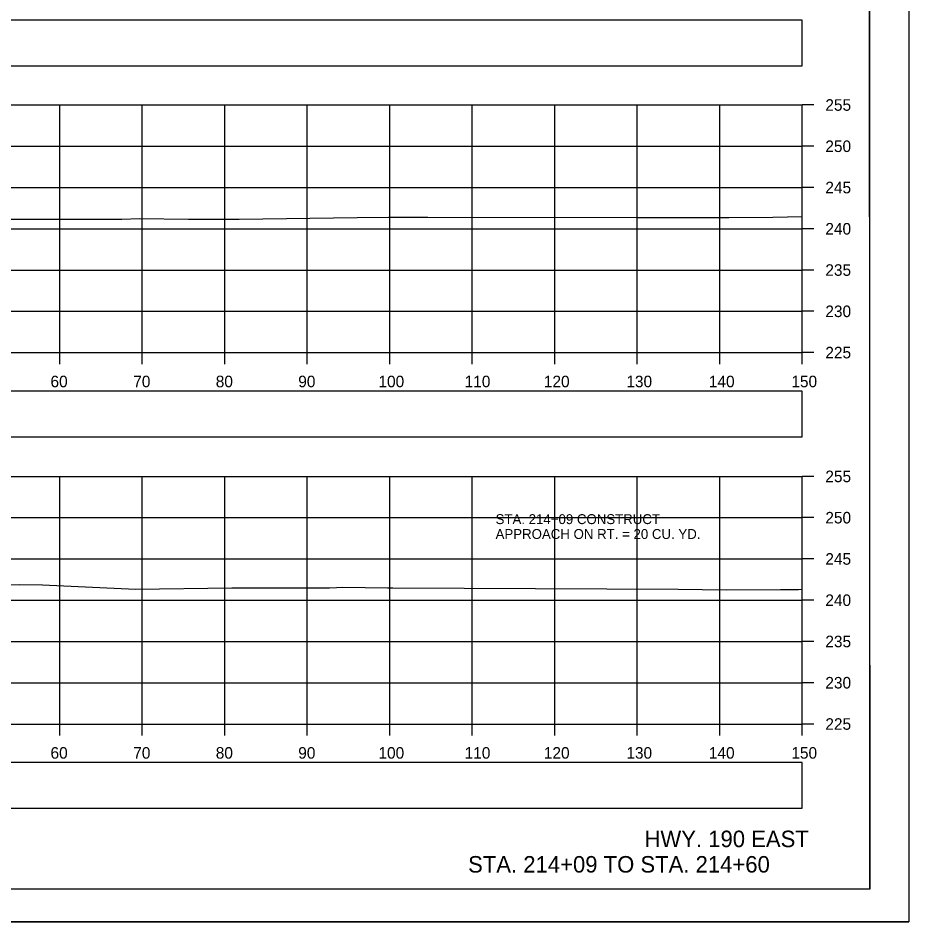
# Model space of a CAD drawing. Extents: x 1369627 to 1374022, y 380035 to 398173.
# Drawn here: x 1372153.5 to 1372261.5, y 383238.9 to 383348.4 of the extents above; entities that cross this region are included whole.
import ezdxf

# ---------------------------------------------------------------- set-up
doc = ezdxf.new("R2010")
doc.units = 0
for name, color, linetype in [('Default', 7, 'Continuous'), ('R_Axis', 7, 'Continuous'), ('R_Axis Annot', 7, 'Continuous'), ('R_Border', 7, 'Continuous'), ('R_Draft', 7, 'Continuous'), ('R_Exist Surface', 7, 'Continuous'), ('R_Grid', 7, 'Continuous'), ('R_No Plot', 7, 'Continuous'), ('R_Water', 7, 'Continuous')]:
    doc.layers.add(name, color=color, linetype=linetype)

msp = doc.modelspace()

# ---------------------------------------------------------------- linework, layer by layer
at = {"layer": 'Default'}
for points in [[(1371948.53, 383342.59), (1372248.53, 383342.59), (1372248.53, 383348.11), (1371948.53, 383348.11)], [(1371948.53, 383297.62), (1372248.53, 383297.62), (1372248.53, 383303.14), (1371948.53, 383303.14)], [(1371948.53, 383252.65), (1372248.53, 383252.65), (1372248.53, 383258.17), (1371948.53, 383258.17)]]:
    msp.add_lwpolyline(points, close=True, dxfattribs=at)
at = {"layer": 'R_Axis'}
for p, q in [((1372248.53, 383307.83), (1372248.53, 383337.83)), ((1372249.93, 383337.83), (1372248.53, 383337.83)), ((1372249.93, 383332.83), (1372248.53, 383332.83)), ((1372249.93, 383327.83), (1372248.53, 383327.83)), ((1372249.93, 383322.83), (1372248.53, 383322.83)), ((1372249.93, 383317.83), (1372248.53, 383317.83)), ((1372249.93, 383312.83), (1372248.53, 383312.83)), ((1371948.53, 383307.83), (1372248.53, 383307.83)), ((1372158.53, 383306.43), (1372158.53, 383307.83)), ((1372168.53, 383306.43), (1372168.53, 383307.83)), ((1372178.53, 383306.43), (1372178.53, 383307.83)), ((1372188.53, 383306.43), (1372188.53, 383307.83)), ((1372198.53, 383306.43), (1372198.53, 383307.83)), ((1372208.53, 383306.43), (1372208.53, 383307.83)), ((1372218.53, 383306.43), (1372218.53, 383307.83)), ((1372228.53, 383306.43), (1372228.53, 383307.83)), ((1372238.53, 383306.43), (1372238.53, 383307.83)), ((1372248.53, 383306.43), (1372248.53, 383307.83)), ((1372249.93, 383307.83), (1372248.53, 383307.83)), ((1372248.53, 383262.83), (1372248.53, 383292.83)), ((1372249.93, 383292.83), (1372248.53, 383292.83)), ((1372249.93, 383287.83), (1372248.53, 383287.83)), ((1372249.93, 383282.83), (1372248.53, 383282.83)), ((1372249.93, 383277.83), (1372248.53, 383277.83)), ((1372249.93, 383272.83), (1372248.53, 383272.83)), ((1372249.93, 383267.83), (1372248.53, 383267.83)), ((1371948.53, 383262.83), (1372248.53, 383262.83)), ((1372158.53, 383261.43), (1372158.53, 383262.83)), ((1372168.53, 383261.43), (1372168.53, 383262.83)), ((1372178.53, 383261.43), (1372178.53, 383262.83)), ((1372188.53, 383261.43), (1372188.53, 383262.83)), ((1372198.53, 383261.43), (1372198.53, 383262.83)), ((1372208.53, 383261.43), (1372208.53, 383262.83)), ((1372218.53, 383261.43), (1372218.53, 383262.83)), ((1372228.53, 383261.43), (1372228.53, 383262.83)), ((1372238.53, 383261.43), (1372238.53, 383262.83)), ((1372248.53, 383261.43), (1372248.53, 383262.83)), ((1372249.93, 383262.83), (1372248.53, 383262.83))]:
    msp.add_line(p, q, dxfattribs=at)
at = {"layer": 'R_Border'}
for q in [(1372256.71, 383448.29), (1371940.53, 383242.83)]:
    msp.add_line((1372256.71, 383242.83), q, dxfattribs=at)
at = {"layer": 'R_Exist Surface'}
for points in [[(1372150.68, 383324.01), (1372162.03, 383324.01), (1372166.04, 383323.98), (1372168.2, 383324.06), (1372174.12, 383323.99), (1372180.28, 383323.98), (1372194.59, 383324.2), (1372198.38, 383324.25), (1372203.14, 383324.25), (1372228.62, 383324.18), (1372239.38, 383324.21), (1372239.62, 383324.21), (1372239.65, 383324.21), (1372244.97, 383324.23), (1372248.53, 383324.31)], [(1372145.41, 383279.71), (1372153.63, 383279.73), (1372156.43, 383279.7), (1372167.73, 383279.17), (1372179.41, 383279.31), (1372191.24, 383279.33), (1372192.07, 383279.38), (1372192.85, 383279.4), (1372198.25, 383279.31), (1372198.54, 383279.31), (1372198.89, 383279.31), (1372233.5, 383279.17), (1372239.31, 383279.08), (1372245.88, 383279.13), (1372248.08, 383279.14), (1372248.53, 383279.15)]]:
    msp.add_lwpolyline(points, dxfattribs=at)
at = {"layer": 'R_Grid'}
for p, q in [((1371948.53, 383337.83), (1372248.53, 383337.83)), ((1372158.53, 383307.83), (1372158.53, 383337.83)), ((1372168.53, 383307.83), (1372168.53, 383337.83)), ((1372178.53, 383307.83), (1372178.53, 383337.83)), ((1372188.53, 383307.83), (1372188.53, 383337.83)), ((1372198.53, 383307.83), (1372198.53, 383337.83)), ((1372208.53, 383307.83), (1372208.53, 383337.83)), ((1372218.53, 383307.83), (1372218.53, 383337.83)), ((1372228.53, 383307.83), (1372228.53, 383337.83)), ((1372238.53, 383307.83), (1372238.53, 383337.83)), ((1372248.53, 383307.83), (1372248.53, 383337.83)), ((1371948.53, 383332.83), (1372248.53, 383332.83)), ((1371948.53, 383327.83), (1372248.53, 383327.83)), ((1371948.53, 383322.83), (1372248.53, 383322.83)), ((1371948.53, 383317.83), (1372248.53, 383317.83)), ((1371948.53, 383312.83), (1372248.53, 383312.83)), ((1371948.53, 383307.83), (1372248.53, 383307.83)), ((1371948.53, 383292.83), (1372248.53, 383292.83)), ((1372158.53, 383262.83), (1372158.53, 383292.83)), ((1372168.53, 383262.83), (1372168.53, 383292.83)), ((1372178.53, 383262.83), (1372178.53, 383292.83)), ((1372188.53, 383262.83), (1372188.53, 383292.83)), ((1372198.53, 383262.83), (1372198.53, 383292.83)), ((1372208.53, 383262.83), (1372208.53, 383292.83)), ((1372218.53, 383262.83), (1372218.53, 383292.83)), ((1372228.53, 383262.83), (1372228.53, 383292.83)), ((1372238.53, 383262.83), (1372238.53, 383292.83)), ((1372248.53, 383262.83), (1372248.53, 383292.83)), ((1371948.53, 383287.83), (1372248.53, 383287.83)), ((1371948.53, 383282.83), (1372248.53, 383282.83)), ((1371948.53, 383277.83), (1372248.53, 383277.83)), ((1371948.53, 383272.83), (1372248.53, 383272.83)), ((1371948.53, 383267.83), (1372248.53, 383267.83)), ((1371948.53, 383262.83), (1372248.53, 383262.83))]:
    msp.add_line(p, q, dxfattribs=at)
at = {"layer": 'R_No Plot'}
msp.add_line((1371928.13, 383238.85), (1372261.46, 383238.85), dxfattribs=at)
for points in [[(1371928.12, 383452.19), (1372261.46, 383452.19), (1372261.46, 383238.85), (1371928.12, 383238.85)], [(1372174.45, 383448.29), (1372194.07, 383448.29), (1372194.07, 383438.41), (1372210.18, 383438.41), (1372233.38, 383438.41), (1372233.38, 383405.74), (1372256.59, 383405.74), (1372256.71, 383242.83), (1371940.53, 383242.83), (1371940.53, 383448.29)]]:
    msp.add_lwpolyline(points, close=True, dxfattribs=at)

# ---------------------------------------------------------------- texts
at = {"layer": 'R_Axis Annot'}
for s, p in [('255', (1372251.33, 383337.13)), ('250', (1372251.33, 383332.13)), ('245', (1372251.33, 383327.13)), ('240', (1372251.33, 383322.13)), ('235', (1372251.33, 383317.13)), ('230', (1372251.33, 383312.13)), ('225', (1372251.33, 383307.13)), ('60', (1372157.41, 383303.63)), ('70', (1372167.44, 383303.63)), ('80', (1372177.44, 383303.63)), ('90', (1372187.44, 383303.63)), ('100', (1372197.16, 383303.63)), ('110', (1372207.61, 383303.63)), ('120', (1372217.21, 383303.63)), ('130', (1372227.21, 383303.63)), ('140', (1372237.21, 383303.63)), ('150', (1372247.21, 383303.63)), ('255', (1372251.33, 383292.13)), ('250', (1372251.33, 383287.13)), ('245', (1372251.33, 383282.13)), ('240', (1372251.33, 383277.13)), ('235', (1372251.33, 383272.13)), ('230', (1372251.33, 383267.13)), ('225', (1372251.33, 383262.13)), ('60', (1372157.41, 383258.63)), ('70', (1372167.44, 383258.63)), ('80', (1372177.44, 383258.63)), ('90', (1372187.44, 383258.63)), ('100', (1372197.16, 383258.63)), ('110', (1372207.61, 383258.63)), ('120', (1372217.21, 383258.63)), ('130', (1372227.21, 383258.63)), ('140', (1372237.21, 383258.63)), ('150', (1372247.21, 383258.63))]:
    msp.add_text(s, height=1.4, dxfattribs=at).set_placement(p)
at = {"layer": 'R_Draft'}
for s, p in [('HWY. 190 EAST', (1372229.41, 383247.91)), ('STA. 214+09 TO STA. 214+60', (1372208.03, 383244.83))]:
    msp.add_text(s, height=2, dxfattribs=at).set_placement(p)
at = {"layer": 'R_Water'}
for s, p in [('STA. 214+09 CONSTRUCT', (1372211.36, 383287.05)), ('APPROACH ON RT. = 20 CU. YD.', (1372211.36, 383285.25))]:
    msp.add_text(s, height=1.2, dxfattribs=at).set_placement(p)

doc.saveas('drawing.dxf')
